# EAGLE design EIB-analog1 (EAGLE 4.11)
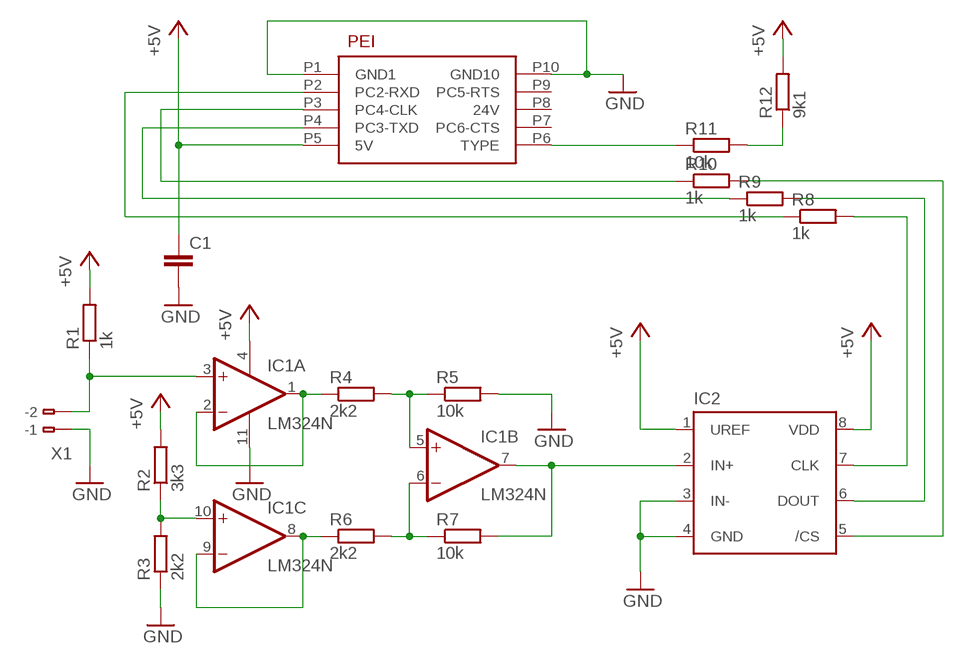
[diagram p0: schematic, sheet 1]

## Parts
C1  C-EU050-035X075  [C050-035X075]
IC1  LM324N  [DIL14]
IC2  MCP3201  [DIL08]
PEI  EIB-PEI  [EIB-PEI]
R1  1k  R-EU_V100  [R100]
R2  3k3  R-EU_V100  [R100]
R3  2k2  R-EU_V100  [R100]
R4  2k2  R-EU_V100  [R100]
R5  10k  R-EU_V100  [R100]
R6  2k2  R-EU_V100  [R100]
R7  10k  R-EU_V100  [R100]
R8  1k  R-EU_V025  [R025]
R9  1k  R-EU_V100  [R100]
R10  1k  R-EU_V025  [R025]
R11  10k  R-EU_V025  [R025]
R12  9k1  R-EU_V025  [R025]
X1  CONN2  [CONN2]

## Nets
+5V: C1.1 IC1.4(P:V+) IC2.1(UREF) IC2.8(VDD) PEI.P5(5V) R1.2 R2.2 R12.2
GND: C1.2 IC1.11(P:V-) IC2.3(IN-) IC2.4(GND) PEI.P1(GND1) PEI.P10(GND10) R3.1 R5.2 X1.A1(-1)
N$1: IC2.5(/CS) R10.2
N$2: IC1.8(C:OUT) IC1.9(C:-IN) R6.1
N$3: PEI.P4(PC3-TXD) R9.1
N$4: IC1.5(B:+IN) R4.2 R5.1
N$5: PEI.P6(TYPE) R11.1
N$6: IC1.3(A:+IN) R1.1 X1.A2(-2)
N$7: IC1.6(B:-IN) R6.2 R7.1
N$8: IC2.6(DOUT) R9.2
N$10: IC1.1(A:OUT) IC1.2(A:-IN) R4.1
N$11: IC1.10(C:+IN) R2.1 R3.2
N$12: IC1.7(B:OUT) IC2.2(IN+) R7.2
N$13: PEI.P2(PC2-RXD) R8.1
N$14: IC2.7(CLK) R8.2
N$15: PEI.P3(PC4-CLK) R10.1
N$16: R11.2 R12.1
Unconnected: IC1.12(D:+IN) IC1.13(D:-IN) IC1.14(D:OUT) PEI.P7(PC6-CTS) PEI.P8(24V) PEI.P9(PC5-RTS)

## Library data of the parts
C1 = rcl:C-EU: CAPACITOR, European symbol
IC1 = linear:LM324: OP AMP
IC2 = ~myDevices:MCP3201: Microchip MCP3201
PEI = ~EIBdevices:EIB-PEI: EIB-PEI 10pol Stecker
R1-R12 = ~myDevices:R-EU_: RESISTOR, European symbol
X1 = ~myDevices:CONN2

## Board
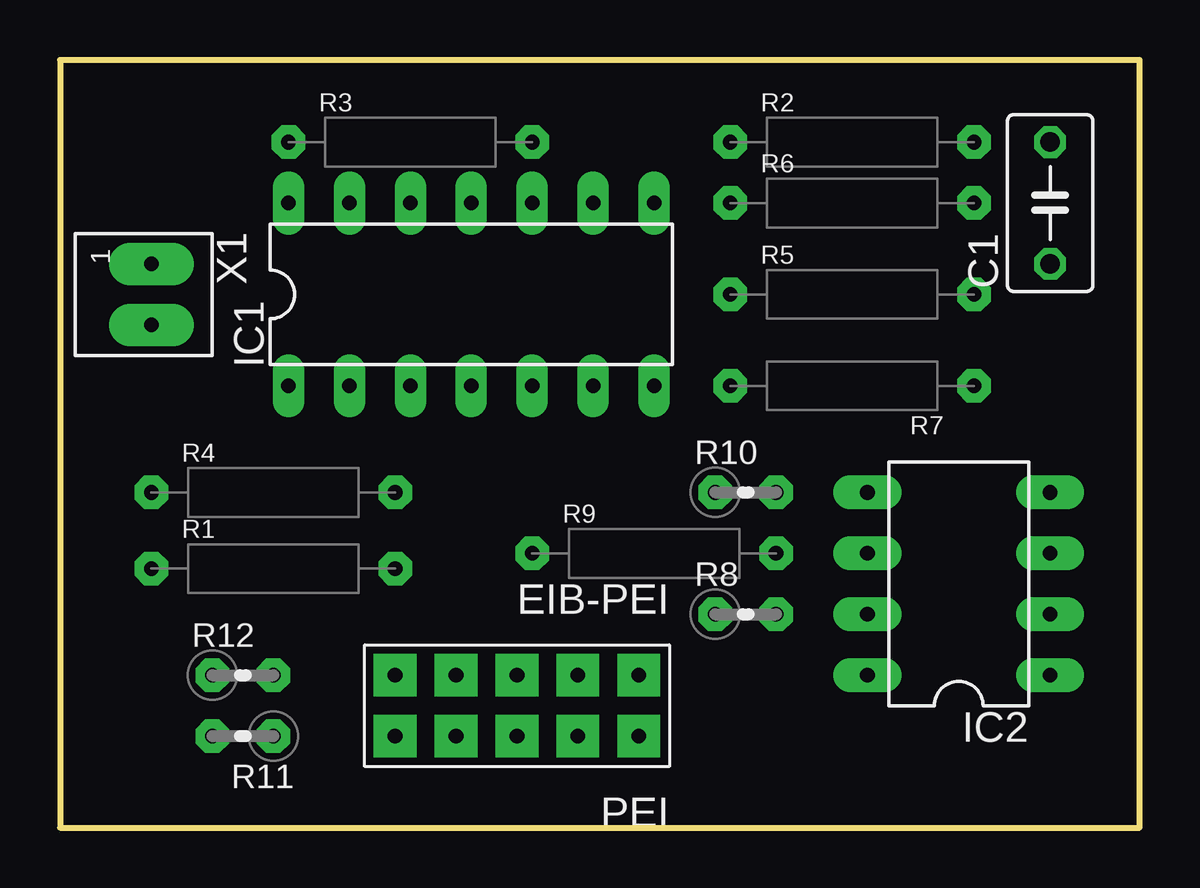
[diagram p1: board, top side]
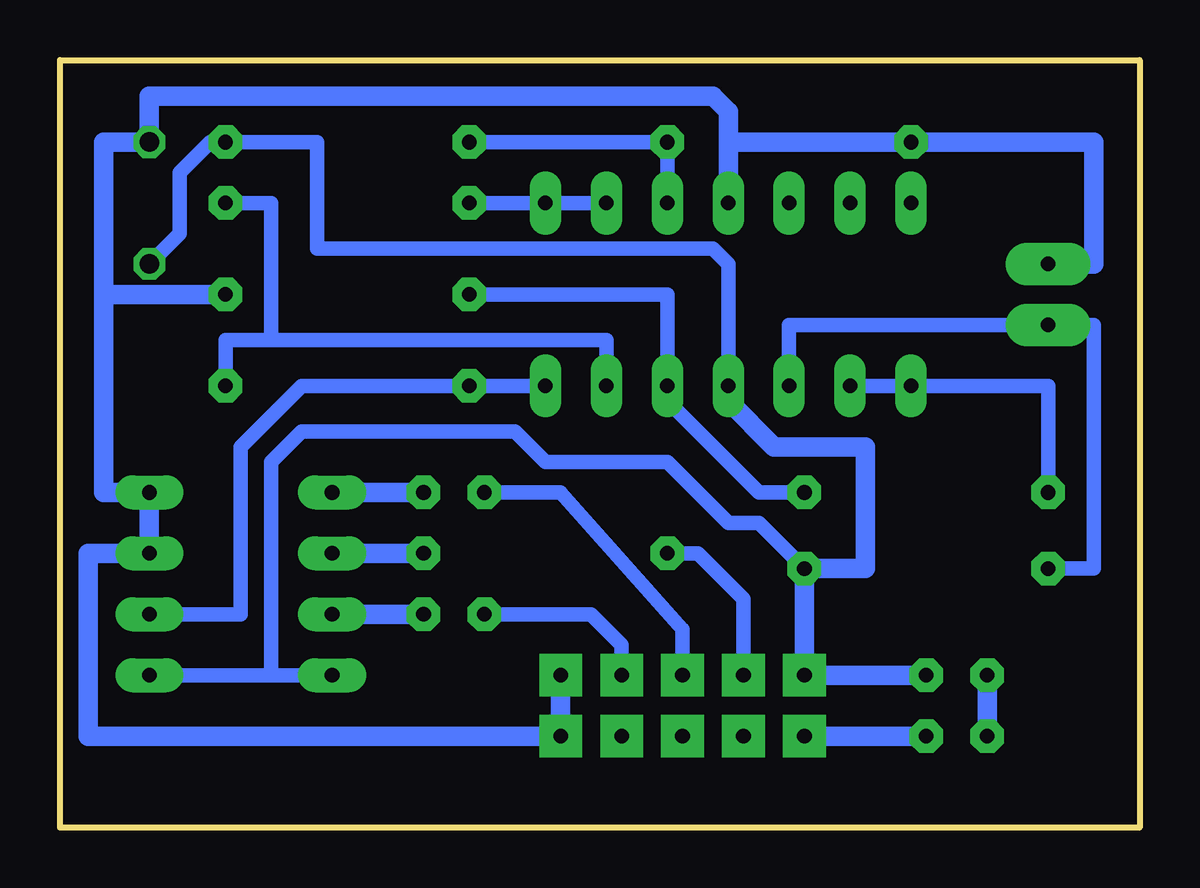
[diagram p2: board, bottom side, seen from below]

Size 45 x 32 mm. Coordinates in mm from the lower left corner, seen from the top.
Outline: 0,0 45,0 45,32 0,32 0,0
Copper layers (1*16): Top 0.035mm / dielectric 1.5mm / Bottom 0.035mm
Design rules "default": minimum track width 10mil, minimum drill 24mil, track to track 8mil, track to pad 8mil, pad to pad 8mil, via to via 8mil, smd to smd 8mil, copper to edge 40mil, drill to drill 8mil, minimum pad ring 10mil, minimum via ring 8mil, stop-mask expansion 4mil, vias tented up to drill 0mil, thermal gap 10mil

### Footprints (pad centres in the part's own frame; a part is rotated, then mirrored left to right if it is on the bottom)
C050-035X075 = drill 0.813 octagon: 1 -2.54,0; 2 2.54,0
DIL14 = drill 0.61 pad 1.321 long: 1 -7.62,-3.81; 2 -5.08,-3.81; 3 -2.54,-3.81; 4 0,-3.81; 5 2.54,-3.81; 6 5.08,-3.81; 7 7.62,-3.81; 8 7.62,3.81; 9 5.08,3.81; 10 2.54,3.81; 11 0,3.81; 12 -2.54,3.81; 13 -5.08,3.81; 14 -7.62,3.81
DIL08 = drill 0.61 pad 1.422 long: 1 -3.81,-3.81; 2 -1.27,-3.81; 3 1.27,-3.81; 4 3.81,-3.81; 5 3.81,3.81; 6 1.27,3.81; 7 -1.27,3.81; 8 -3.81,3.81
EIB-PEI = drill 0.61 pad 1.778 square: P1 -1.27,0; P2 1.27,0; P3 3.81,0; P4 6.35,0; P5 8.89,0; P6 8.89,2.54; P7 6.35,2.54; P8 3.81,2.54; P9 1.27,2.54; P10 -1.27,2.54
R100 = drill 0.61 pad 1.397 octagon: 1 -3.81,0; 2 6.35,0
R025 = drill 0.61 pad 1.397 octagon: 1 -1.27,0; 2 1.27,0
CONN2 = drill 0.61 pad 1.778 long: A1 -1.27,2.54; A2 1.27,2.543

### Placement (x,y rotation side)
C1  41.27,26.04 90 top
IC1  17.14,22.23 0 top
IC2  37.47,10.16 90 top
PEI  22.86,6.35 180 top
R1  7.62,10.79 0 top
R2  31.75,28.57 0 top
R3  13.34,28.57 0 top
R4  7.62,13.97 0 top
R5  31.75,22.23 0 top
R6  31.75,26.04 0 top
R7  34.29,18.41 180 top
R8  28.57,8.89 0 top
R9  23.5,11.43 0 top
R10  28.57,13.97 0 top
R11  7.62,3.81 180 top
R12  7.62,6.35 0 top
X1  1.27,22.23 270 top

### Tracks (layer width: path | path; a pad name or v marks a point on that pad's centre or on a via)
+5V
  Bottom 0.61: 36.2,6.35 IC2.1 | IC1.4 17.14,23.5 17.78,24.13 34.29,24.13 34.29,28.57 R2.2 38.73,28.57 40.01,27.3 40.01,24.77 C1.1 | 36.2,6.35 IC2.8 | 36.2,6.35 36.2,15.24 34.92,16.51 26.04,16.51 24.77,15.24 19.68,15.24 17.14,12.7 15.88,12.7 R1.2
  Bottom 0.813: R12.2 PEI.P5 R1.2 11.43,10.79 11.43,15.88 15.24,15.88 17.14,17.78 IC1.4
GND
  Bottom 0.61: 17.14,28.57 IC1.11 | 1.91,23.5
  Bottom 0.813: 43.18,22.23 43.18,13.97 IC2.4 IC2.3 43.81,11.43 43.81,3.81 PEI.P10 PEI.P1 | 43.18,22.23 R5.2 | X1.A1 1.91,23.5 1.91,28.57 R3.1 17.14,28.57 | IC1.11 17.14,29.84 17.78,30.48 41.27,30.48 C1.2 43.18,28.57 43.18,22.23
N$1
  Bottom 0.813: R10.2 IC2.5
N$2
  Bottom 0.61: IC1.9 IC1.8 R6.1
N$3
  Bottom 0.61: PEI.P4 16.51,9.53 18.41,11.43 R9.1
N$4
  Bottom 0.61: R4.2 15.88,13.97 19.68,17.78 IC1.5 19.68,22.23 R5.1
N$5
  Bottom 0.813: R11.1 PEI.P6
N$6
  Bottom 0.61: X1.A2 14.61,20.95 IC1.3 | X1.A2 | X1.A2 1.91,20.95 1.91,10.79 R1.1
N$7
  Bottom 0.61: IC1.6 22.23,20.32 36.2,20.32 | 36.2,20.32 38.1,20.32 R7.1 | 36.2,20.32 36.2,26.04 R6.2
N$8
  Bottom 0.813: R9.2 IC2.6
N$10
  Bottom 0.61: IC1.2 IC1.1 3.81,18.41 R4.1
N$11
  Bottom 0.61: IC1.10 R3.2 R2.1
N$12
  Bottom 0.61: IC2.2 37.47,8.89 37.47,15.88 34.92,18.41 R7.2 IC1.7
N$13
  Bottom 0.61: PEI.P2 21.59,7.62 22.86,8.89 R8.1
N$14
  Bottom 0.813: R8.2 IC2.7
N$15
  Bottom 0.61: PEI.P3 19.05,8.26 24.13,13.97 R10.1
N$16
  Bottom 0.813: R11.2 R12.1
